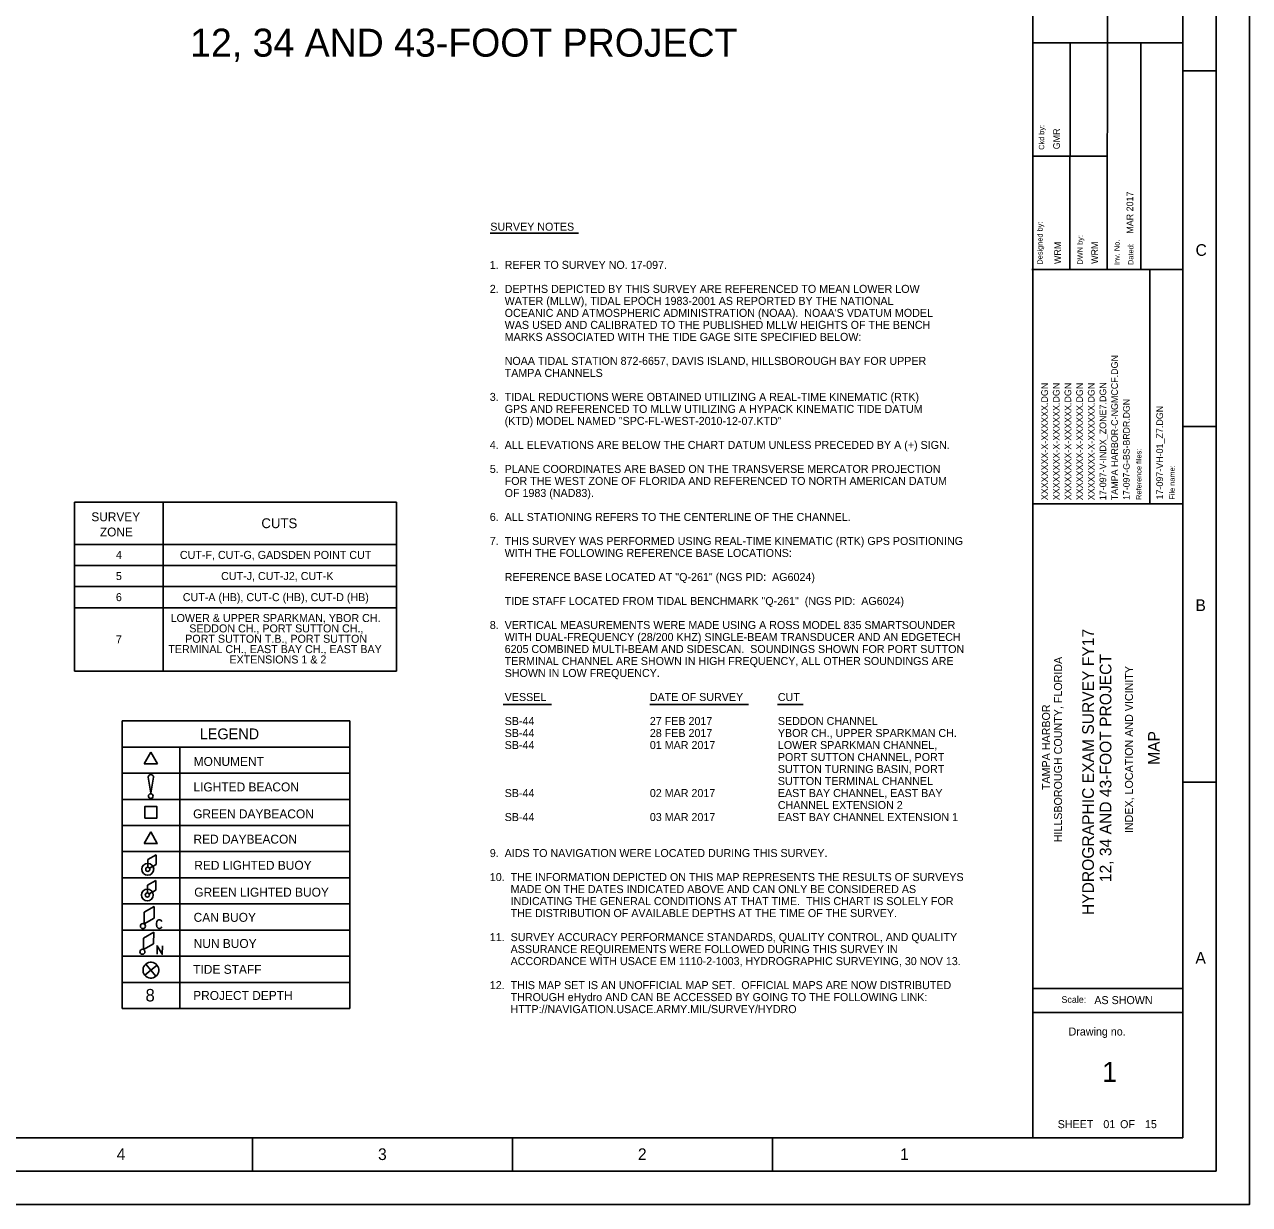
# Model space of a CAD drawing. Extents: x 452225 to 584229, y 1232161 to 1334160.
# Drawn here: x 529114 to 584229, y 1232161 to 1285243 of the extents above; entities that cross this region are included whole.
import ezdxf

# ---------------------------------------------------------------- set-up
doc = ezdxf.new("R2010")
doc.units = 0
for name, color, linetype in [('G-ANNO-NPLT', 7, 'Continuous'), ('G-ANNO-TEXT-DRWG', 7, 'Continuous'), ('G-ANNO-TEXT-PROJ', 7, 'Continuous'), ('G-ANNO-TEXT-TTLB', 7, 'Continuous'), ('G-ANNO-TTLB', 7, 'Continuous'), ('V-ANNO-LEGN', 7, 'Continuous'), ('V-ANNO-SCHD', 7, 'Continuous'), ('V-ANNO-TEXT', 7, 'Continuous')]:
    doc.layers.add(name, color=color, linetype=linetype)

msp = doc.modelspace()

# ---------------------------------------------------------------- linework, layer by layer
at = {"layer": 'G-ANNO-NPLT'}
msp.add_lwpolyline([(452225, 1334160), (584225, 1334160), (584225, 1232161), (452225, 1232161)], close=True, dxfattribs=at)
msp.add_lwpolyline([(584229, 1233661), (584229, 1232161), (582729, 1232161)], dxfattribs=at)
at = {"layer": 'G-ANNO-TTLB'}
for p, q in [((574474, 1331160), (574474, 1235161)), ((577830, 1274225), (577850, 1300012)), ((574451, 1284415), (581225, 1284415)), ((576151, 1274227), (576159, 1284415)), ((579336, 1284415), (579336, 1274225)), ((582725, 1283157), (581225, 1283157)), ((574451, 1279320), (577834, 1279320)), ((574438, 1274225), (581225, 1274225)), ((579746, 1274225), (579746, 1263684)), ((582725, 1267158), (581225, 1267158)), ((574474, 1263684), (581225, 1263684)), ((582725, 1251160), (581225, 1251160)), ((574474, 1241874), (581225, 1241874)), ((574474, 1240803), (581225, 1240803)), ((539375, 1233661), (539375, 1235161)), ((551075, 1233661), (551075, 1235161)), ((562775, 1233661), (562775, 1235161))]:
    msp.add_line(p, q, dxfattribs=at)
for points in [[(453725, 1233661), (582725, 1233661), (582725, 1332660), (453725, 1332660)], [(581225, 1331160), (457475, 1331160), (457475, 1235161), (581225, 1235161)]]:
    msp.add_lwpolyline(points, close=True, dxfattribs=at)
at = {"layer": 'V-ANNO-LEGN'}
for p, q in [((533504, 1253916), (533504, 1240973)), ((533504, 1253916), (543754, 1253916)), ((543754, 1253916), (543754, 1240973)), ((533504, 1252739), (543754, 1252739)), ((534504, 1251989), (534804, 1252504)), ((534804, 1252504), (535098, 1251990)), ((536099, 1252734), (536099, 1240973)), ((535100, 1251987), (534504, 1251989)), ((533504, 1251562), (543754, 1251562)), ((534799, 1250670), (534673, 1251382)), ((534924, 1251382), (534799, 1250670)), ((533504, 1250387), (543754, 1250387)), ((533504, 1249210), (543754, 1249210)), ((534496, 1248406), (534795, 1248921)), ((534795, 1248921), (535090, 1248407)), ((535091, 1248404), (534496, 1248406)), ((533504, 1248033), (543754, 1248033)), ((534660, 1247678), (535039, 1247897)), ((535039, 1247897), (535039, 1247459)), ((534660, 1247334), (534660, 1247678)), ((535039, 1247459), (534741, 1247287)), ((533504, 1246857), (543754, 1246857)), ((534642, 1246521), (535021, 1246740)), ((535021, 1246740), (535021, 1246302)), ((534642, 1246177), (534642, 1246521)), ((535021, 1246302), (534723, 1246130)), ((533504, 1245680), (543754, 1245680)), ((534496, 1245306), (534947, 1245567)), ((534497, 1244784), (534496, 1245306)), ((534948, 1245046), (534497, 1244784)), ((534947, 1245567), (534948, 1245046)), ((533504, 1244503), (543754, 1244503)), ((534472, 1243627), (534474, 1244149)), ((534474, 1244149), (534927, 1244408)), ((534927, 1244408), (534925, 1243886)), ((534925, 1243886), (534472, 1243627)), ((533504, 1243327), (543754, 1243327)), ((534574, 1242978), (534801, 1242704)), ((534801, 1242704), (535076, 1242932)), ((534801, 1242704), (534527, 1242476)), ((535029, 1242430), (534801, 1242704)), ((533504, 1242150), (543754, 1242150)), ((533504, 1240973), (543754, 1240973))]:
    msp.add_line(p, q, dxfattribs=at)
msp.add_lwpolyline([(534532, 1249535), (534532, 1250066), (535063, 1250065), (535063, 1249534)], close=True, dxfattribs=at)
for points in [[(535294, 1244889), (535246, 1244951), (535198, 1244963), (535165, 1244963), (535120, 1244951), (535070, 1244888), (535058, 1244804), (535058, 1244759), (535058, 1244729), (535061, 1244703), (535070, 1244655), (535121, 1244595), (535166, 1244583), (535193, 1244583), (535244, 1244595), (535295, 1244655)], [(535078, 1243420), (535079, 1243800), (535314, 1243419), (535316, 1243799)]]:
    msp.add_lwpolyline(points, dxfattribs=at)
for centre, radius in [((534797, 1250535), 107), ((534660, 1247240), 266), ((534660, 1247240), 93.7), ((534642, 1246083), 266), ((534642, 1246083), 93.7), ((534443, 1244686), 112), ((534418, 1243530), 112)]:
    msp.add_circle(centre, radius, dxfattribs=at)
for centre, radius, start, end in [((534799, 1251372), 126, 4.6442, 175.3545), ((534801, 1242704), 356, 129.6858, 219.6858), ((534801, 1242704), 356, 39.6856, 129.6858), ((534801, 1242704), 356, 309.6858, 39.6859), ((534801, 1242704), 356, 219.6858, 309.6858)]:
    msp.add_arc(centre, radius, start, end, dxfattribs=at)
at = {"layer": 'V-ANNO-SCHD'}
for p, q in [((531360, 1263758), (531360, 1256155)), ((531360, 1263758), (545849, 1263758)), ((535351, 1263758), (535351, 1256155)), ((545849, 1263758), (545849, 1256155)), ((531360, 1261858), (545849, 1261858)), ((531360, 1260907), (545849, 1260907)), ((531360, 1259957), (545849, 1259957)), ((531360, 1259006), (545849, 1259006)), ((531360, 1256155), (545849, 1256155))]:
    msp.add_line(p, q, dxfattribs=at)
at = {"layer": 'V-ANNO-TEXT'}
for p, q in [((550072, 1275859), (554046, 1275859)), ((550647, 1254653), (552818, 1254653)), ((557249, 1254653), (561688, 1254653)), ((562998, 1254653), (564150, 1254653))]:
    msp.add_line(p, q, dxfattribs=at)

# ---------------------------------------------------------------- texts
at = {"layer": 'G-ANNO-TEXT-DRWG'}
for s, height, p in [('GMR', 300, (575696, 1279630)), ('WRM', 300, (575742, 1274468)), ('WRM', 300, (577411, 1274475)), ('TAMPA HARBOR-C-NGMCCF.DGN', 300, (578307, 1263844)), ('XXXXXXXX-X-XXXXXX.DGN', 300, (575157, 1263844)), ('XXXXXXXX-X-XXXXXX.DGN', 300, (575682, 1263844)), ('XXXXXXXX-X-XXXXXX.DGN', 300, (576207, 1263844)), ('XXXXXXXX-X-XXXXXX.DGN', 300, (576732, 1263844)), ('XXXXXXXX-X-XXXXXX.DGN', 300, (577257, 1263844)), ('17-097-V-INDX_ZONE7.DGN', 300, (577782, 1263844)), ('17-097-VH-01_Z7.DGN', 300, (580338, 1263875)), ('INDEX, LOCATION AND VICINITY', 360, (578986, 1248868)), ('MAP', 524.9, (580192, 1251937))]:
    msp.add_text(s, height=height, rotation=90, dxfattribs=at).set_placement(p)
for s, height, p in [('1', 900, (577599, 1237675)), (' 01          15', 360, (577519, 1235595))]:
    msp.add_text(s, height=height, dxfattribs=at).set_placement(p)
at = {"layer": 'G-ANNO-TEXT-PROJ'}
for s, height, p in [('MAR 2017', 300, (578997, 1275833)), ('17-097-G-BS-BRDR.DGN', 294, (578837, 1263856)), ('HYDROGRAPHIC EXAM SURVEY FY17', 525, (577227, 1245180)), ('HILLSBOROUGH COUNTY, FLORIDA', 360, (575795, 1248452)), ('12, 34 AND 43-FOOT PROJECT', 525, (578015, 1246662)), ('TAMPA HARBOR', 360, (575255, 1250804))]:
    msp.add_text(s, height=height, rotation=90, dxfattribs=at).set_placement(p)
at = {"layer": 'G-ANNO-TEXT-TTLB'}
for s, p in [('Ckd by:', (574992, 1279605)), ('Designed by:', (574919, 1274443)), ('DWN by:', (576725, 1274444)), ('Inv. No.', (578382, 1274422)), ('Dated:', (579006, 1274425)), ('Reference files:', (579368, 1263858)), ('File name:', (580867, 1263866))]:
    msp.add_text(s, height=240, rotation=90, dxfattribs=at).set_placement(p)
for s, height, p in [('Scale:', 300, (575768, 1241232)), ('AS SHOWN', 360, (577248, 1241175)), ('Drawing no.', 360, (576089, 1239762)), ('SHEET         OF', 360, (575598, 1235595))]:
    msp.add_text(s, height=height, dxfattribs=at).set_placement(p)
at = {"layer": 'G-ANNO-TTLB'}
for s, p in [('C', (581802, 1274835)), ('B', (581796, 1258859)), ('A', (581796, 1242996)), ('4', (533265, 1234161)), ('3', (545020, 1234161)), ('2', (556713, 1234161)), ('1', (568507, 1234161))]:
    msp.add_text(s, height=525, dxfattribs=at).set_placement(p)
at = {"layer": 'V-ANNO-LEGN'}
for s, height, p in [('LEGEND', 486.7, (536996, 1253088)), ('MONUMENT', 401.5, (536724, 1251890)), ('LIGHTED BEACON', 401.54, (536717, 1250743)), ('GREEN DAYBEACON', 401.54, (536701, 1249533)), ('RED DAYBEACON', 401.54, (536717, 1248394)), ('RED LIGHTED BUOY', 401.54, (536752, 1247219)), ('GREEN LIGHTED BUOY', 401.54, (536752, 1246009)), ('CAN BUOY', 401.5, (536724, 1244878)), ('NUN BUOY', 401.5, (536724, 1243701)), ('TIDE STAFF', 401.5, (536704, 1242538)), ('8', 563, (534558, 1241294)), ('PROJECT DEPTH', 401.54, (536704, 1241364))]:
    msp.add_text(s, height=height, rotation=360, dxfattribs=at).set_placement(p)
at = {"layer": 'V-ANNO-SCHD'}
for s, height, p in [('SURVEY', 399.1, (532122, 1262898)), ('CUTS', 443.5, (539773, 1262586)), ('ZONE', 399.1, (532507, 1262214)), ('4', 360, (533228, 1261202)), ('CUT-F, CUT-G, GADSDEN POINT CUT', 360, (536106, 1261202)), ('5', 360, (533226, 1260252)), ('CUT-J, CUT-J2, CUT-K', 360, (537960, 1260252)), ('6', 360, (533227, 1259302)), ('CUT-A (HB), CUT-C (HB), CUT-D (HB)', 360, (536237, 1259302)), ('LOWER & UPPER SPARKMAN, YBOR CH.', 360, (535689, 1258363)), ('SEDDON CH., PORT SUTTON CH.,', 360, (536528, 1257897)), ('7', 360, (533227, 1257401)), ('PORT SUTTON T.B., PORT SUTTON', 360, (536345, 1257431)), ('TERMINAL CH., EAST BAY CH., EAST BAY ', 360, (535585, 1256965)), ('EXTENSIONS 1 & 2', 360, (538335, 1256499))]:
    msp.add_text(s, height=height, rotation=360, dxfattribs=at).set_placement(p)
at = {"layer": 'V-ANNO-TEXT'}
for s, height, p in [('12, 34 AND 43-FOOT PROJECT', 1260, (536568, 1283796)), ('SURVEY NOTES', 360, (550072, 1275968)), ('1.  REFER TO SURVEY NO. 17-097.', 360, (550049, 1274250)), ('2.  DEPTHS DEPICTED BY THIS SURVEY ARE REFERENCED TO MEAN LOWER LOW', 360, (550049, 1273170)), ('     WATER (MLLW), TIDAL EPOCH 1983-2001 AS REPORTED BY THE NATIONAL', 360, (550049, 1272630)), ("     OCEANIC AND ATMOSPHERIC ADMINISTRATION (NOAA).  NOAA'S VDATUM MODEL", 360, (550049, 1272090)), ('     WAS USED AND CALIBRATED TO THE PUBLISHED MLLW HEIGHTS OF THE BENCH', 360, (550049, 1271550)), ('     MARKS ASSOCIATED WITH THE TIDE GAGE SITE SPECIFIED BELOW:    ', 360, (550049, 1271010)), ('     NOAA TIDAL STATION 872-6657, DAVIS ISLAND, HILLSBOROUGH BAY FOR UPPER', 360, (550049, 1269930)), ('     TAMPA CHANNELS  ', 360, (550049, 1269390)), ('3.  TIDAL REDUCTIONS WERE OBTAINED UTILIZING A REAL-TIME KINEMATIC (RTK)', 360, (550049, 1268310)), ('     GPS AND REFERENCED TO MLLW UTILIZING A HYPACK KINEMATIC TIDE DATUM', 360, (550049, 1267770)), ('     (KTD) MODEL NAMED "SPC-FL-WEST-2010-12-07.KTD"', 360, (550049, 1267230)), ('4.  ALL ELEVATIONS ARE BELOW THE CHART DATUM UNLESS PRECEDED BY A (+) SIGN.', 360, (550049, 1266150)), ('5.  PLANE COORDINATES ARE BASED ON THE TRANSVERSE MERCATOR PROJECTION', 360, (550049, 1265070)), ('     FOR THE WEST ZONE OF FLORIDA AND REFERENCED TO NORTH AMERICAN DATUM', 360, (550049, 1264530)), ('     OF 1983 (NAD83).', 360, (550049, 1263990)), ('6.  ALL STATIONING REFERS TO THE CENTERLINE OF THE CHANNEL.', 360, (550049, 1262910)), ('7.  THIS SURVEY WAS PERFORMED USING REAL-TIME KINEMATIC (RTK) GPS POSITIONING', 360, (550049, 1261830)), ('     WITH THE FOLLOWING REFERENCE BASE LOCATIONS:', 360, (550049, 1261290)), ('     REFERENCE BASE LOCATED AT "Q-261" (NGS PID:  AG6024)', 360, (550049, 1260210)), ('     TIDE STAFF LOCATED FROM TIDAL BENCHMARK "Q-261"  (NGS PID:  AG6024)', 360, (550049, 1259130)), ('8.  VERTICAL MEASUREMENTS WERE MADE USING A ROSS MODEL 835 SMARTSOUNDER', 360, (550049, 1258050)), ('     WITH DUAL-FREQUENCY (28/200 KHZ) SINGLE-BEAM TRANSDUCER AND AN EDGETECH', 360, (550049, 1257510)), ('     6205 COMBINED MULTI-BEAM AND SIDESCAN.  SOUNDINGS SHOWN FOR PORT SUTTON', 360, (550049, 1256970)), ('     TERMINAL CHANNEL ARE SHOWN IN HIGH FREQUENCY, ALL OTHER SOUNDINGS ARE ', 360, (550049, 1256430)), ('     SHOWN IN LOW FREQUENCY.  ', 360, (550049, 1255890)), ('     VESSEL', 360, (550049, 1254810)), ('DATE OF SURVEY', 360, (557249, 1254810)), ('CUT', 360, (563009, 1254810)), ('     SB-44', 360, (550049, 1253730)), ('27 FEB 2017 ', 360, (557249, 1253730)), ('SEDDON CHANNEL', 360, (563009, 1253730)), ('     SB-44', 360, (550049, 1253190)), ('28 FEB 2017', 360, (557249, 1253190)), ('YBOR CH., UPPER SPARKMAN CH.', 360, (563009, 1253190)), ('     SB-44', 360, (550049, 1252650)), ('01 MAR 2017', 360, (557249, 1252650)), ('LOWER SPARKMAN CHANNEL,', 360, (563009, 1252650)), ('PORT SUTTON CHANNEL, PORT', 360, (563009, 1252110)), ('SUTTON TURNING BASIN, PORT', 360, (563009, 1251570)), ('SUTTON TERMINAL CHANNEL', 360, (563009, 1251030)), ('     SB-44', 360, (550049, 1250490)), ('02 MAR 2017', 360, (557249, 1250490)), ('EAST BAY CHANNEL, EAST BAY', 360, (563009, 1250490)), ('CHANNEL EXTENSION 2', 360, (563009, 1249950)), ('     SB-44', 360, (550049, 1249410)), ('03 MAR 2017', 360, (557249, 1249410)), ('EAST BAY CHANNEL EXTENSION 1 ', 360, (563009, 1249410)), ('9.  AIDS TO NAVIGATION WERE LOCATED DURING THIS SURVEY.', 360, (550049, 1247790)), ('10.  THE INFORMATION DEPICTED ON THIS MAP REPRESENTS THE RESULTS OF SURVEYS', 360, (550049, 1246710)), ('       MADE ON THE DATES INDICATED ABOVE AND CAN ONLY BE CONSIDERED AS', 360, (550049, 1246170)), ('       INDICATING THE GENERAL CONDITIONS AT THAT TIME.  THIS CHART IS SOLELY FOR', 360, (550049, 1245630)), ('       THE DISTRIBUTION OF AVAILABLE DEPTHS AT THE TIME OF THE SURVEY.', 360, (550049, 1245090)), ('11.  SURVEY ACCURACY PERFORMANCE STANDARDS, QUALITY CONTROL, AND QUALITY', 360, (550049, 1244010)), ('       ASSURANCE REQUIREMENTS WERE FOLLOWED DURING THIS SURVEY IN', 360, (550049, 1243470)), ('       ACCORDANCE WITH USACE EM 1110-2-1003, HYDROGRAPHIC SURVEYING, 30 NOV 13.    ', 360, (550049, 1242930)), ('12.  THIS MAP SET IS AN UNOFFICIAL MAP SET.  OFFICIAL MAPS ARE NOW DISTRIBUTED', 360, (550049, 1241850)), ('       THROUGH eHydro AND CAN BE ACCESSED BY GOING TO THE FOLLOWING LINK:', 360, (550049, 1241310)), ('       HTTP://NAVIGATION.USACE.ARMY.MIL/SURVEY/HYDRO', 360, (550049, 1240770))]:
    msp.add_text(s, height=height, dxfattribs=at).set_placement(p)

doc.saveas('drawing.dxf')
